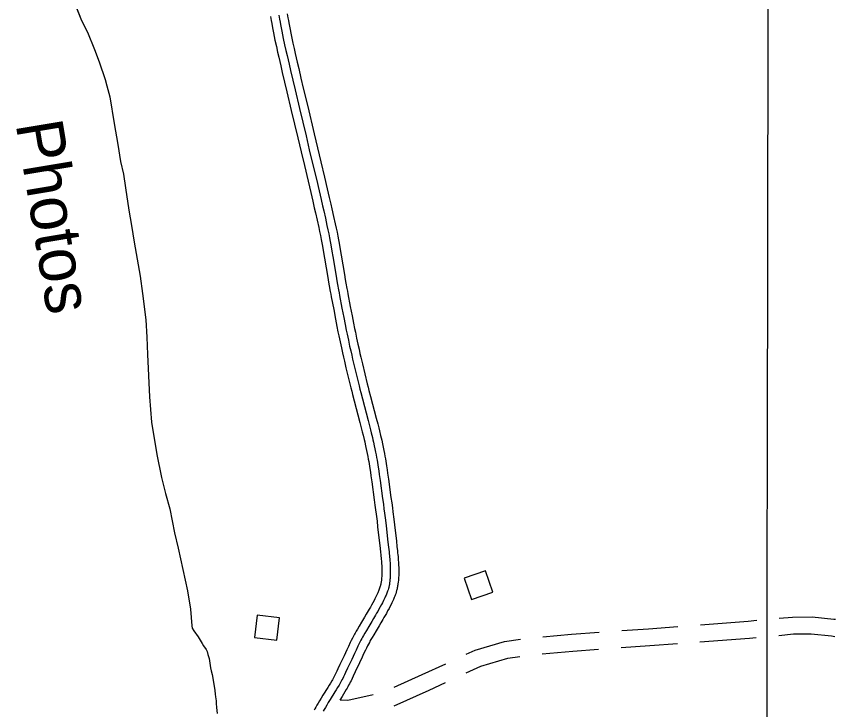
# Model space of a CAD drawing. Extents: x 3192952 to 3230831, y 849296 to 874698.
# Drawn here: x 3211521 to 3212972, y 862444 to 863672 of the extents above; entities that cross this region are included whole.
import ezdxf

# ---------------------------------------------------------------- set-up
doc = ezdxf.new("R2010")
doc.units = 0
for name, color, linetype in [('V-BLDG-OTLN', 7, 'Continuous'), ('V-GRID-MAJR', 7, 'Continuous'), ('V-RIVR-IDEN', 7, 'Continuous'), ('V-ROAD-CNTR', 7, 'Continuous'), ('V-SITE-VEGE', 7, 'Continuous'), ('V-TOPO-SHOR', 7, 'Continuous')]:
    doc.layers.add(name, color=color, linetype=linetype)

msp = doc.modelspace()

# ---------------------------------------------------------------- linework, layer by layer
at = {"layer": 'V-BLDG-OTLN'}
for points in [[(3212327.1, 862639.3), (3212364.8, 862652.6), (3212351.6, 862690.3), (3212313.8, 862677)], [(3211987.3, 862607), (3211947.6, 862612), (3211942.6, 862572.3), (3211982.3, 862567.3)]]:
    msp.add_lwpolyline(points, close=True, dxfattribs=at)
at = {"layer": 'V-GRID-MAJR'}
msp.add_spline([(3212836, 854703.6), (3212847.5, 860762.7), (3212858.9, 866825.2), (3212870.4, 872887.8), (3212870.4, 872891.2)], degree=3, dxfattribs=at)
at = {"layer": 'V-ROAD-CNTR'}
for points in [[(3211971.3, 863671.9), (3211972.4, 863664.7), (3211973.4, 863659.2), (3211974.1, 863655.1), (3211975.3, 863648.9), (3211976.5, 863642.8), (3211977.8, 863636.1), (3211979.1, 863630), (3211981.6, 863618.4), (3211983.8, 863608.3), (3211985.7, 863599.5), (3211989.2, 863584.2), (3211991.9, 863572.6), (3211995.9, 863555.4), (3212000, 863538.2), (3212007.8, 863505.6), (3212019.5, 863456.7), (3212025.3, 863432.2), (3212031.2, 863407.8), (3212037.7, 863380.4), (3212042.5, 863359.9), (3212046.1, 863344.5), (3212048.7, 863333), (3212050.7, 863324.4), (3212053.6, 863311.4), (3212056.5, 863298.4), (3212058.1, 863290.9), (3212059.5, 863283.8), (3212060.8, 863277.1), (3212062, 863270.8), (3212063.1, 863265), (3212065.1, 863253.8), (3212066.7, 863244.1), (3212072.5, 863209.7), (3212074, 863201.1), (3212075.1, 863194.6), (3212076.9, 863184.9), (3212077.8, 863180), (3212078.7, 863175.1), (3212083, 863152.7), (3212086.2, 863135.8), (3212088.7, 863123.1), (3212090.6, 863113.6), (3212092.1, 863106.5), (3212094.3, 863095.8), (3212096.6, 863085.1), (3212098.6, 863076.2), (3212100.4, 863068.4), (3212102, 863061.6), (3212104.8, 863049.8), (3212113.4, 863014.5), (3212114.9, 863008.1), (3212116.4, 863002.2), (3212119.3, 862991.1), (3212129.5, 862952.7), (3212131.9, 862943.2), (3212133.7, 862936.1), (3212135.1, 862930.7), (3212137, 862922.7), (3212138, 862918.7), (3212138.9, 862914.7), (3212140.2, 862908.7), (3212141.4, 862903), (3212142.4, 862897.7), (3212143.4, 862892.7), (3212144.2, 862888), (3212145, 862883.6), (3212145.7, 862879.5), (3212146.9, 862871.6), (3212148, 862864.7), (3212148.9, 862858.7), (3212150.4, 862848.1), (3212154.8, 862816.1), (3212156.1, 862806.5), (3212157.2, 862798.1), (3212158.2, 862790.8), (3212159.8, 862777.9), (3212160.9, 862768.2), (3212164.3, 862739.1), (3212165.3, 862730.2), (3212166.2, 862722.4), (3212166.5, 862719.1), (3212166.8, 862715.9), (3212167.1, 862713), (3212167.3, 862710.3), (3212167.5, 862707.8), (3212167.8, 862702.8)], [(3211986.1, 863674.3), (3211987.2, 863667.2), (3211988.2, 863661.8), (3211988.9, 863657.8), (3211990, 863651.7), (3211991.2, 863645.7), (3211992.5, 863639.2), (3211993.8, 863633), (3211996.2, 863621.6), (3211998.4, 863611.6), (3212000.4, 863602.8), (3212003.9, 863587.5), (3212006.5, 863576), (3212010.5, 863558.9), (3212014.6, 863541.7), (3212022.4, 863509.1), (3212034.1, 863460.2), (3212039.9, 863435.7), (3212045.8, 863411.3), (3212052.3, 863383.9), (3212057.1, 863363.3), (3212060.7, 863347.9), (3212063.4, 863336.4), (3212065.3, 863327.7), (3212068.3, 863314.7), (3212071.1, 863301.6), (3212072.8, 863293.9), (3212074.2, 863286.7), (3212075.6, 863279.9), (3212076.8, 863273.6), (3212077.9, 863267.6), (3212079.8, 863256.4), (3212081.5, 863246.6), (3212087.3, 863212.2), (3212088.8, 863203.6), (3212089.9, 863197.2), (3212091.6, 863187.6), (3212092.5, 863182.7), (3212093.4, 863177.9), (3212097.7, 863155.5), (3212100.9, 863138.7), (3212103.4, 863126.1), (3212105.3, 863116.6), (3212106.8, 863109.5), (3212109, 863098.9), (3212111.3, 863088.3), (3212113.2, 863079.5), (3212115, 863071.8), (3212116.6, 863065.1), (3212119.4, 863053.3), (3212128, 863018), (3212129.5, 863011.8), (3212131, 863005.9), (3212133.8, 862994.9), (3212144, 862956.5), (3212146.5, 862946.9), (3212148.3, 862939.7), (3212149.6, 862934.3), (3212151.6, 862926.2), (3212152.6, 862922.1), (3212153.5, 862918), (3212154.9, 862911.8), (3212156.1, 862906), (3212157.1, 862900.5), (3212158.1, 862895.4), (3212159, 862890.6), (3212159.8, 862886.1), (3212160.5, 862881.9), (3212161.7, 862873.9), (3212162.8, 862867), (3212163.7, 862860.9), (3212165.2, 862850.2), (3212169.7, 862818.1), (3212171, 862808.5), (3212172.1, 862800), (3212173.1, 862792.6), (3212174.6, 862779.7), (3212175.8, 862770), (3212179.2, 862740.8), (3212180.2, 862731.9), (3212181.1, 862724), (3212181.4, 862720.6), (3212181.7, 862717.4), (3212182, 862714.3), (3212182.3, 862711.5), (3212182.5, 862708.8), (3212182.8, 862703.8)], [(3212000.9, 863676.7), (3212002, 863669.6), (3212002.9, 863664.4), (3212003.6, 863660.5), (3212004.7, 863654.6), (3212005.9, 863648.7), (3212007.2, 863642.2), (3212008.5, 863636.1), (3212010.9, 863624.7), (3212013.1, 863614.8), (3212015, 863606.1), (3212018.5, 863590.9), (3212021.1, 863579.4), (3212025.1, 863562.3), (3212029.2, 863545.1), (3212037, 863512.5), (3212048.7, 863463.7), (3212054.5, 863439.2), (3212060.3, 863414.7), (3212066.8, 863387.3), (3212071.7, 863366.8), (3212075.3, 863351.3), (3212078, 863339.7), (3212080, 863331), (3212082.9, 863317.9), (3212085.8, 863304.8), (3212087.5, 863297), (3212089, 863289.6), (3212090.3, 863282.8), (3212091.5, 863276.3), (3212092.6, 863270.3), (3212094.6, 863259), (3212096.3, 863249.1), (3212102.1, 863214.7), (3212103.5, 863206.2), (3212104.7, 863199.8), (3212106.4, 863190.2), (3212107.2, 863185.5), (3212108.1, 863180.7), (3212112.4, 863158.3), (3212115.7, 863141.5), (3212118.1, 863129), (3212120, 863119.6), (3212121.5, 863112.6), (3212123.7, 863102), (3212125.9, 863091.5), (3212127.9, 863082.8), (3212129.6, 863075.2), (3212131.2, 863068.5), (3212134, 863056.8), (3212142.5, 863021.6), (3212144.1, 863015.4), (3212145.5, 863009.6), (3212148.3, 862998.7), (3212158.5, 862960.3), (3212161, 862950.7), (3212162.8, 862943.4), (3212164.2, 862937.9), (3212166.2, 862929.6), (3212167.2, 862925.5), (3212168.1, 862921.3), (3212169.5, 862914.9), (3212170.8, 862909), (3212171.9, 862903.4), (3212172.9, 862898.1), (3212173.7, 862893.2), (3212174.5, 862888.6), (3212175.3, 862884.3), (3212176.6, 862876.3), (3212177.6, 862869.2), (3212178.6, 862863), (3212180.1, 862852.3), (3212184.5, 862820.2), (3212185.9, 862810.5), (3212187, 862802), (3212188, 862794.5), (3212189.5, 862781.5), (3212190.7, 862771.7), (3212194.1, 862742.5), (3212195.1, 862733.5), (3212196, 862725.6), (3212196.3, 862722.1), (3212196.7, 862718.8), (3212197, 862715.6), (3212197.2, 862712.7), (3212197.4, 862709.9), (3212197.8, 862704.8)], [(3212167.8, 862703.1), (3212168, 862698.8), (3212168.2, 862695.2), (3212168.2, 862692.1), (3212168.2, 862689.4), (3212168.2, 862687.1), (3212168.2, 862685), (3212168.1, 862683.2), (3212168, 862680.1), (3212167.8, 862677.8), (3212167.7, 862676.1), (3212167.4, 862673.5), (3212167.1, 862670.9), (3212167, 862669.7), (3212166.8, 862668.5), (3212166.6, 862667.4), (3212166.3, 862666.3), (3212166.1, 862665.2), (3212165.8, 862664.2), (3212165.6, 862663.2), (3212165, 862661.2), (3212164.4, 862659.3), (3212163.8, 862657.5), (3212163.2, 862655.9), (3212162.5, 862654.3), (3212161.9, 862652.8), (3212161.3, 862651.4), (3212160.1, 862648.7), (3212159, 862646.4), (3212157.9, 862644.3), (3212156, 862640.6), (3212154.6, 862637.9), (3212152.3, 862633.6), (3212149.9, 862629.3), (3212148, 862625.7), (3212146.1, 862622.4), (3212144.3, 862619.3), (3212140.8, 862613.5), (3212137.8, 862608.4), (3212132.3, 862599.3), (3212128.1, 862592.4), (3212125, 862587.1), (3212122.8, 862583.1), (3212121.1, 862580.1), (3212119.8, 862577.8), (3212117.9, 862574.3), (3212116.1, 862570.8), (3212114.2, 862566.8), (3212112.4, 862563.1), (3212109.1, 862556.3), (3212106.2, 862550.3), (3212101.3, 862539.8), (3212094.1, 862524.2), (3212090.5, 862516.5), (3212088.7, 862512.7), (3212086.8, 862508.9), (3212085.6, 862506.5), (3212084.4, 862504.1), (3212083.1, 862501.8), (3212081.9, 862499.6), (3212080.7, 862497.5), (3212079.5, 862495.4), (3212077.1, 862491.3), (3212074.8, 862487.5), (3212072.6, 862483.9), (3212063.9, 862470.2), (3212060.6, 862464.9), (3212057.7, 862460.2), (3212055.3, 862456), (3212053.2, 862452.2), (3212051.3, 862448.9), (3212049.8, 862445.9), (3212048.4, 862443.3)], [(3212182.8, 862703.8), (3212183, 862699.5), (3212183.1, 862695.7), (3212183.2, 862692.3), (3212183.2, 862689.4), (3212183.2, 862686.8), (3212183.2, 862684.6), (3212183.1, 862682.7), (3212182.9, 862679.2), (3212182.8, 862676.7), (3212182.6, 862674.8), (3212182.3, 862671.9), (3212182, 862669), (3212181.8, 862667.5), (3212181.6, 862666), (3212181.3, 862664.5), (3212181, 862663.1), (3212180.7, 862661.8), (3212180.4, 862660.5), (3212180, 862659.2), (3212179.3, 862656.8), (3212178.6, 862654.5), (3212177.9, 862652.4), (3212177.1, 862650.5), (3212176.4, 862648.7), (3212175.7, 862647), (3212175, 862645.4), (3212173.7, 862642.4), (3212172.4, 862639.8), (3212171.3, 862637.6), (3212169.3, 862633.7), (3212167.8, 862630.8), (3212165.4, 862626.4), (3212163.1, 862622.1), (3212161.1, 862618.4), (3212159.1, 862615), (3212157.3, 862611.8), (3212153.7, 862605.8), (3212150.6, 862600.6), (3212145.1, 862591.5), (3212141, 862584.8), (3212138, 862579.6), (3212135.8, 862575.8), (3212134.2, 862572.8), (3212133, 862570.6), (3212131.2, 862567.3), (3212129.5, 862564), (3212127.6, 862560.2), (3212125.8, 862556.6), (3212122.6, 862549.8), (3212119.8, 862543.9), (3212114.9, 862533.5), (3212107.7, 862517.9), (3212104, 862510.1), (3212102.2, 862506.2), (3212100.3, 862502.3), (3212099, 862499.7), (3212097.6, 862497.1), (3212096.3, 862494.7), (3212095, 862492.3), (3212093.7, 862490), (3212092.5, 862487.8), (3212090, 862483.6), (3212087.6, 862479.7), (3212085.3, 862476), (3212076.6, 862462.3), (3212073.4, 862457.1), (3212070.6, 862452.5), (3212068.3, 862448.5), (3212066.3, 862444.9), (3212064.6, 862441.8)], [(3212197.8, 862704.6), (3212198, 862700.1), (3212198.1, 862696.1), (3212198.2, 862692.5), (3212198.2, 862689.4), (3212198.2, 862686.6), (3212198.2, 862684.2), (3212198.1, 862682.1), (3212197.9, 862678.4), (3212197.7, 862675.6), (3212197.6, 862673.5), (3212197.3, 862670.3), (3212196.9, 862667.2), (3212196.6, 862665.3), (3212196.3, 862663.4), (3212196, 862661.6), (3212195.7, 862659.9), (3212195.3, 862658.3), (3212194.9, 862656.7), (3212194.5, 862655.2), (3212193.7, 862652.4), (3212192.8, 862649.7), (3212192, 862647.3), (3212191.1, 862645.1), (3212190.3, 862643), (3212189.5, 862641.1), (3212188.7, 862639.3), (3212187.3, 862636.1), (3212185.9, 862633.3), (3212184.7, 862630.8), (3212182.6, 862626.7), (3212181, 862623.7), (3212178.6, 862619.3), (3212176.3, 862614.9), (3212174.2, 862611.1), (3212172.1, 862607.5), (3212170.2, 862604.2), (3212166.6, 862598.1), (3212163.4, 862592.8), (3212158, 862583.8), (3212153.9, 862577.1), (3212151, 862572.1), (3212148.9, 862568.4), (3212147.3, 862565.6), (3212146.2, 862563.5), (3212144.5, 862560.4), (3212142.9, 862557.2), (3212141.1, 862553.5), (3212139.3, 862550), (3212136.1, 862543.4), (3212133.4, 862537.5), (3212128.5, 862527.2), (3212121.3, 862511.5), (3212117.6, 862503.6), (3212115.7, 862499.7), (3212113.8, 862495.7), (3212112.3, 862492.9), (3212110.9, 862490.1), (3212109.5, 862487.5), (3212108.1, 862485), (3212106.8, 862482.6), (3212105.4, 862480.2), (3212102.8, 862475.9), (3212100.3, 862471.8), (3212098, 862468), (3212093.7, 862461.3)], [(3212732.6, 862594.8), (3212816.9, 862601.1), (3212832.3, 862602.6)], [(3212872.1, 862606.2), (3212895.7, 862608.4), (3212930, 862608.8), (3212968.4, 862604.9), (3212971.8, 862604.4)], [(3212453.4, 862573.6), (3212504.3, 862578), (3212553.1, 862581.5)], [(3212593, 862584.4), (3212640.7, 862587.8), (3212692.7, 862591.7)], [(3212317.7, 862542.7), (3212333.3, 862549.9), (3212385.2, 862564.8), (3212413.7, 862569.2)], [(3212731.6, 862564.6), (3212819.4, 862571.2), (3212831.3, 862572.3)], [(3212871.1, 862576), (3212897.3, 862578.4), (3212928.7, 862578.8), (3212964.7, 862575.1), (3212970.7, 862574.2)], [(3212592, 862554.2), (3212642.9, 862557.9), (3212691.7, 862561.6)], [(3212317.6, 862509.5), (3212343.8, 862521.7), (3212391.6, 862535.4), (3212412.7, 862538.6)], [(3212452.4, 862543.4), (3212506.6, 862548.1), (3212552.1, 862551.4)], [(3212190.4, 862484.4), (3212239.8, 862506.5), (3212281.4, 862525.8)], [(3212190.2, 862451.4), (3212252.2, 862479.2), (3212281.3, 862492.7)], [(3212094.3, 862462), (3212108, 862461.5), (3212152.8, 862471.4)]]:
    msp.add_lwpolyline(points, dxfattribs=at)
at = {"layer": 'V-SITE-VEGE'}
for p, q in [((3211616, 863717.3), (3211636.2, 863664.7)), ((3211636.2, 863664.7), (3211646.8, 863643.9)), ((3211646.8, 863643.9), (3211659.4, 863613.4)), ((3211659.4, 863613.4), (3211667.6, 863591.3)), ((3211667.6, 863591.3), (3211678.4, 863560.1)), ((3211678.4, 863560.1), (3211681.5, 863549.1)), ((3211681.5, 863549.1), (3211686.6, 863529.5)), ((3211686.6, 863529.5), (3211694.5, 863482.3)), ((3211694.5, 863482.3), (3211701, 863444.9)), ((3211701, 863444.9), (3211705.6, 863414.9)), ((3211705.6, 863414.9), (3211710.7, 863392.8)), ((3211710.7, 863392.8), (3211714.6, 863368.3)), ((3211714.6, 863368.3), (3211720.5, 863329.1)), ((3211720.5, 863329.1), (3211725.1, 863301.5)), ((3211725.1, 863301.5), (3211729.7, 863272.1)), ((3211729.7, 863272.1), (3211740.1, 863212)), ((3211740.1, 863212), (3211744.7, 863181.4)), ((3211744.7, 863181.4), (3211750.1, 863134.8)), ((3211750.1, 863134.8), (3211752.2, 863104.1)), ((3211752.2, 863104.1), (3211753.1, 863073.4)), ((3211753.1, 863073.4), (3211756.9, 862998.5)), ((3211756.9, 862998.5), (3211760.4, 862953.7)), ((3211760.4, 862953.7), (3211769.6, 862896.1)), ((3211769.6, 862896.1), (3211778, 862855.7)), ((3211778, 862855.7), (3211785, 862826.9)), ((3211785, 862826.9), (3211792.6, 862800)), ((3211792.6, 862800), (3211801, 862757.7)), ((3211801, 862757.7), (3211807.5, 862730.1)), ((3211807.5, 862730.1), (3211824.2, 862654.8)), ((3211824.2, 862654.8), (3211829.4, 862622.3)), ((3211829.4, 862622.3), (3211831.8, 862592.6)), ((3211831.8, 862592.6), (3211832.4, 862588.9)), ((3211832.4, 862588.9), (3211835.5, 862584.1)), ((3211835.5, 862584.1), (3211843.3, 862573.4)), ((3211843.3, 862573.4), (3211850, 862561.3)), ((3211850, 862561.3), (3211852.5, 862557.3)), ((3211852.5, 862557.3), (3211857.2, 862550.8)), ((3211857.2, 862550.8), (3211859.2, 862547.2)), ((3211859.2, 862547.2), (3211860.1, 862541.9)), ((3211860.1, 862541.9), (3211862.3, 862535.2)), ((3211862.3, 862535.2), (3211865.1, 862518.3)), ((3211865.1, 862518.3), (3211866.1, 862513.2)), ((3211866.1, 862513.2), (3211867.6, 862506.5)), ((3211867.6, 862506.5), (3211872, 862482.5)), ((3211872, 862482.5), (3211872.4, 862478.4)), ((3211872.4, 862478.4), (3211873.2, 862472.1)), ((3211873.2, 862472.1), (3211873.9, 862467.3)), ((3211873.9, 862467.3), (3211874.7, 862460.2)), ((3211874.7, 862460.2), (3211875, 862455.3)), ((3211875, 862455.3), (3211875.8, 862448.5)), ((3211875.8, 862448.5), (3211876.5, 862437.7))]:
    msp.add_line(p, q, dxfattribs=at)
at = {"layer": 'V-TOPO-SHOR'}
for points in [[(3211616, 863717.3), (3211636.2, 863664.7), (3211646.8, 863643.9), (3211659.4, 863613.4), (3211667.6, 863591.3), (3211678.4, 863560.1)], [(3211678.4, 863560.1), (3211681.5, 863549.1), (3211686.6, 863529.5), (3211694.5, 863482.3), (3211701, 863444.9), (3211705.6, 863414.9), (3211710.7, 863392.8), (3211714.6, 863368.3), (3211720.5, 863329.1), (3211725.1, 863301.5), (3211729.7, 863272.1), (3211740.1, 863212), (3211744.7, 863181.4), (3211750.1, 863134.8), (3211752.2, 863104.1), (3211753.1, 863073.4), (3211756.9, 862998.5), (3211760.4, 862953.7), (3211769.6, 862896.1), (3211778, 862855.7), (3211785, 862826.9), (3211792.6, 862800), (3211801, 862757.7), (3211807.5, 862730.1), (3211824.2, 862654.8), (3211829.4, 862622.3), (3211831.8, 862592.6)], [(3211831.8, 862592.6), (3211832.4, 862588.9), (3211835.5, 862584.1), (3211843.3, 862573.4), (3211850, 862561.3), (3211852.5, 862557.3), (3211857.2, 862550.8), (3211859.2, 862547.2), (3211860.1, 862541.9), (3211862.3, 862535.2), (3211865.1, 862518.3), (3211866.1, 862513.2), (3211867.6, 862506.5), (3211872, 862482.5), (3211872.4, 862478.4), (3211873.2, 862472.1), (3211873.9, 862467.3), (3211874.7, 862460.2), (3211875, 862455.3), (3211875.8, 862448.5), (3211876.5, 862437.7)]]:
    msp.add_lwpolyline(points, dxfattribs=at)

# ---------------------------------------------------------------- texts
at = {"layer": 'V-RIVR-IDEN'}
msp.add_text('Photos', height=83, rotation=279.4734, dxfattribs=at).set_placement((3211519.7, 863481.6))

doc.saveas('drawing.dxf')
